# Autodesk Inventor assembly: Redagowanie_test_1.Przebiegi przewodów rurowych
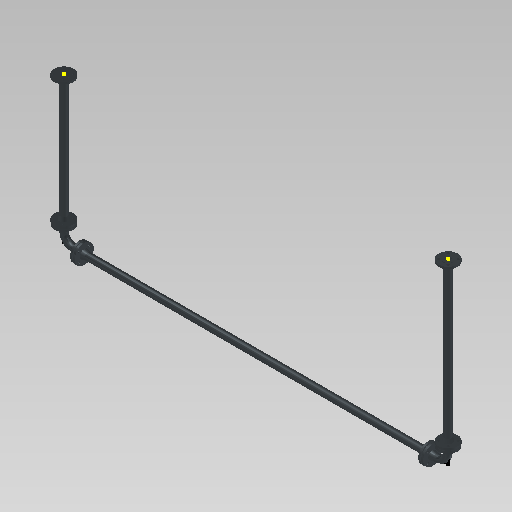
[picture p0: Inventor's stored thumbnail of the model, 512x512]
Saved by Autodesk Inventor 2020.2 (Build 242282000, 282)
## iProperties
ActiveState: False
Angle: UnInitValue
BendRadius: 12,700 mm
CouplingKey: UnInitValue
DefaultBendRadius: UnInitValue
Diameter: 1/2
DiameterType: Nominal
Elbow45Key: UnInitValue
Elbow90Key: UnInitValue
ElbowCustomKey: UnInitValue
EndFittingKey: v3#933069c9-73b6-4141-af99-628d4a97b2c2#1
Ending: UnInitValue
FittingMaterial: UnInitValue
FittingStandard: UnInitValue
FlangeKey: UnInitValue
Gap: UnInitValue
GasketKey: UnInitValue
ID: 1,27
IntermediateSegmentsInc: UnInitValue
IntermediateSegmentsMax: UnInitValue
IntermediateSegmentsMin: UnInitValue
IsButtWelded: UnInitValue
IsFlanged: UnInitValue
IsSelfDraining: UnInitValue
Material: UnInitValue
MixedUnits: UnInitValue
Name: Przewód hydrauliczny – złączki kołnierzowe SAE
OD: 2,2352
PipeKey: v3#d489867e-ac9b-47ea-b952-0a1b885f66be#4
PipeType: Flexible Hose
PipingComponentColor: As Material
RoundUpValue: 3,175 mm
RouteDirection45: UnInitValue
RouteDirection90: UnInitValue
Schedule: ID=0.5
ShowGap: UnInitValue
Standard: UnInitValue
StartFittingKey: v3#933069c9-73b6-4141-af99-628d4a97b2c2#1
SuppressEndFitting: False
SuppressStartFitting: False
TerminationSegmentsInc: UnInitValue
TerminationSegmentsMax: UnInitValue
TerminationSegmentsMin: UnInitValue
UseFlangsForCouplings: UnInitValue
UseSubASM: True
_ComponentInfo: <CS><C N="Pipe" R="1.117600" OR="1.117600" IR="0.635000" PL="PL" PartType="" SymKey="" PN="Parker Hydraulic Hose - No Skive 1/2"><CO N="1"><FE V="0"/><FD V="0"/
BendRadius: UnInitValue
CouplingKey: v3#52ad3977-2b89-4007-a6a6-7626bac0ae85#4
Elbow45Key: v3#5c2ab816-abcb-49a6-a106-4733af000f51#4
Elbow90Key: v3#160eac10-3e6f-4b5c-839c-61eee0d373dc#4
EndFittingKey: UnInitValue
ID: UnInitValue
IntermediateSegmentsInc: 2,540 mm
IntermediateSegmentsMax: 5080,000 mm
IntermediateSegmentsMin: 50,800 mm
IsButtWelded: False
IsFlanged: False
IsSelfDraining: False
MixedUnits: False
Name: ASME B36.10M-ASME B16.11 - Rury stalowe gwintowane
OD: UnInitValue
PipeKey: v3#4a736116-503a-44ad-a922-868ac6b46736#1
PipeType: Rigid Pipe
RoundUpValue: UnInitValue
RouteDirection45: True
RouteDirection90: True
Schedule: 30
StartFittingKey: UnInitValue
SuppressEndFitting: UnInitValue
SuppressStartFitting: UnInitValue
TerminationSegmentsInc: 2,540 mm
TerminationSegmentsMax: 5080,000 mm
TerminationSegmentsMin: 50,800 mm
UseSubASM: UnInitValue
_ComponentInfo: <CS><C N="Pipe" R="1.066800" IR="0.825500" PL="PL" PN="ASME B36.10M Pipe with Threaded Ends 1/2 - Schedule 30"><CO N="1"><FE V="0"/><FD V="1"/><ET V="Threaded"/
Name: Przewód hydrauliczny – bez złączek
SuppressEndFitting: True
SuppressStartFitting: True
Diameter: M40
Elbow45Key: v3#97879d80-057e-491b-840b-74a9b3a7cf63#17
Elbow90Key: v3#ace818b0-7b7c-4ad9-b19c-6da358a202c1#17
IntermediateSegmentsInc: 1,000 mm
IntermediateSegmentsMax: 5000,000 mm
IntermediateSegmentsMin: 60,000 mm
Name: DIN 2458/DIN 2605 - Rury stalowe spawane i łączniki
PipeKey: v3#dcef2839-8903-4c98-a96c-b861f5d9bb7f#98
Schedule: ID=30.7
TerminationSegmentsInc: 1,000 mm
TerminationSegmentsMax: 5000,000 mm
TerminationSegmentsMin: 60,000 mm
_ComponentInfo: <CS><C N="Pipe" R="2.415000" IR="1.535000" PL="PL" PN="DIN 2458 Pipe 48.3 x 8.8"><CO N="1"><FE V="2"/><FD V="0"/><ET V="Welded"/><NS V="M40"/><MA V="0.000000"/>
CouplingKey: v3#181262db-c004-4877-bc40-c64b931a44f6#3
Elbow45Key: v3#960407aa-00b9-4d72-aae7-d50595845cfd#3
Elbow90Key: v3#6c92b367-65e9-486b-b952-db434ae2548d#3
IntermediateSegmentsMin: 20,000 mm
Name: JIS G 3442/JIS B 2301 - Rury stalowe gwintowane ze stalowymi łącznikami
PipeKey: v3#9964fba4-9d5a-4d75-85a8-e38022ccdce1#2
Schedule: ID=16.1
TerminationSegmentsMin: 20,000 mm
_ComponentInfo: <CS><C N="Pipe" R="1.085000" IR="0.805000" PL="PL" PN="JIS G 3442 Pipe with Threaded Ends 21.7 x 2.8"><CO N="1"><FE V="0"/><FD V="1"/><ET V="Threaded"/><NS V="1
Angle: 92,00 deg
Diameter: 1
Elbow45Key: v3#bf26aa2a-f3dd-474c-8758-922a145c2b02#15
Elbow90Key: v3#3e93288f-9bb7-4e46-9d6b-544f8c20ca1c#3
ElbowCustomKey: v3#1f3bd44a-47ab-42f9-b3e0-74afa0c3f0ca#3
Gap: 2,388 mm
IntermediateSegmentsInc: 0.00001 in
IsButtWelded: True
IsSelfDraining: True
Name: ASME BPE - Rura stalowa kołnierzowa
PipeKey: v3#b10c956f-6fc6-429e-8056-0864a8581764#35
Schedule: ID=0.87
ShowGap: True
TerminationSegmentsInc: 0.00001 in
_ComponentInfo: <CS><C N="Pipe" R="1.270000" OR="1.270000" IR="1.104900" PL="PL" PartType="pipe" SymKey="" PN="ASTM A 269 Tube with Welded ends 1 x 0.87"><CO N="1"><FE V="2"/><
Diameter: 6
Elbow90Key: v3#97ecdcaf-8aa3-4fb0-8b6a-3da783de2ad5#108
Gap: 1,575 mm
IntermediateSegmentsMin: 76,200 mm
Name: ASTM A 53/A-ASME B16.9 - Rura stalowa ze szwem
PipeKey: v3#4ce5e9fa-6da0-4801-ac02-ee7a0fb518d6#77
RouteDirection45: False
Schedule: 40
TerminationSegmentsMin: 76,200 mm
_ComponentInfo: <CS><C N="Elbow90" ER="15.240000" S1="15.240000" S2="15.240000" D1="0.000000" D2="0.000000" PartType="fitting" SymKey="ELBW"><CO N="1"><FE V="2"/><FD V="0"/><ET
EndFittingKey: v3#c5e461f5-5e73-4f2e-8c1e-4358d4d6f46c#4
Name: Przewód hydrauliczny – gwint wewnętrzny - obrotowy
StartFittingKey: v3#c5e461f5-5e73-4f2e-8c1e-4358d4d6f46c#4
Manager: www.cadconsulting.pl
Company: Fabian Stasiak CAD Consulting
CouplingKey: v3#3edf83e2-464b-4b31-84c5-c329ffbf2a4f#5
Elbow45Key: v3#2f597a97-b15b-49d4-87cb-7bfe69eb62ee#5
Elbow90Key: v3#fbd68fd5-590c-4cb5-8c20-9e9bdd396a04#5
Name: DIN 8062/DIN 8063 - Rury i złączki PCV-U
PipeKey: v3#3d294dc7-89c3-4c37-a0ae-28c15a73bfd0#13
Schedule: 5
_ComponentInfo: <CS><C N="Pipe" R="2.000000" IR="1.700000" PL="PL" PN="DIN 8062 Pipe 40 x 3"><CO N="1"><FE V="0"/><FD V="0"/><ET V="Jointed"/><NS V="M40"/><MA V="8.000000"/><MI
EndFittingKey: v3#cc3bd835-95a2-497d-9893-176cd9c426f6#7
Name: Przewód hydrauliczny – gwint stożkowy wewnętrzny
StartFittingKey: v3#cc3bd835-95a2-497d-9893-176cd9c426f6#7
EndFittingKey: v3#b50cb43e-68c0-48ac-8e25-7ef224ce0e6c#3
Name: Przewód hydrauliczny – gwint zewnętrzny prosty
StartFittingKey: v3#b50cb43e-68c0-48ac-8e25-7ef224ce0e6c#3
CouplingKey: v3#eaa8de87-dc67-4eca-ba7e-4267a30f8f7f#2
Elbow45Key: v3#2769403e-a4fd-4a4c-8e4c-659ea845bd78#2
Elbow90Key: v3#c4513a61-3106-4a78-baf9-a1badd100245#2
IntermediateSegmentsMax: 2500,000 mm
Name: JIS K 6741/JIS K 6739 - Rury i złączki PCV-U
PipeKey: v3#45338dd0-af69-48c0-a2ed-8ade33a08701#5
Schedule: VP
TerminationSegmentsMax: 2500,000 mm
_ComponentInfo: <CS><C N="Pipe" R="2.400000" IR="2.040000" PL="PL" PN="JIS K 6741 Pipe VP 40"><CO N="1"><FE V="0"/><FD V="1"/><ET V="Jointed"/><NS V="M40"/><MA V="4.000000"/><M
CouplingKey: v3#7e56b2cb-a132-4546-b8a7-a14538454b94#3
Elbow45Key: v3#a96c5204-26e4-4bb2-b8f1-f0623fbc94bb#2
Elbow90Key: v3#b72bb08b-ad33-47cc-a03d-7f3d76c6616b#3
Name: ISO 7598/ISO 49 - Rury stalowe gwintowane ze stalowymi łącznikami
PipeKey: v3#1052637f-74b5-47f4-adeb-d4e8d3fa53b8#1
_ComponentInfo: <CS><C N="Pipe" R="1.065000" IR="0.805000" PL="PL" PN="ISO 7598 Tube with Threaded Ends DN15"><CO N="1"><FE V="0"/><FD V="1"/><ET V="Threaded"/><NS V="1/2"/><MA
EndFittingKey: v3#c8250148-a7b6-458b-b7bd-3b56763ca7cc#13
Name: Przewód hydrauliczny – gwint stożkowy zewnętrzny
StartFittingKey: v3#c8250148-a7b6-458b-b7bd-3b56763ca7cc#13
Elbow90Key: v3#6a678020-d9d9-4685-bba9-906b9a167083#10
FlangeKey: v3#24991861-26e3-4c21-a713-f46e314eddd5#10
GasketKey: v3#2a41914c-f5fb-4682-9c6a-1870d826d3d0#23
IsFlanged: True
Name: ASTM A 53/A 53M - Rura stalowa kołnierzowa/spawana doczołowo
UseFlangsForCouplings: False
_ComponentInfo: <CS><C N="Pipe" R="8.413750" OR="8.413750" IR="7.702550" PL="PL" PartType="pipe" SymKey="" PN="ASTM A 53/A 53M Pipe 6 - Schedule 40"><CO N="1"><FE V="2"/><FD V=
CouplingKey: v3#12b64993-10e6-4915-8315-0c0cce209ad0#8
Elbow45Key: v3#28e76e79-e22c-40ab-8be2-ff545b1407c5#8
Elbow90Key: v3#1f65ece3-c41a-48d4-8661-909ed34ade86#8
Name: JIS G 3458/JIS B 2316 - Rury stalowe spawane i łączniki
PipeKey: v3#da14b0ab-0b36-4851-8d66-8c9cd0bcbe86#23
Schedule: 80
_ComponentInfo: <CS><C N="Pipe" R="2.430000" IR="1.920000" PL="PL" PN="JIS G 3458 Pipe 40 A x Sch 80"><CO N="1"><FE V="0"/><FD V="1"/><ET V="Welded"/><NS V="M40"/><MA V="0.0000
CouplingKey: v3#ed415c76-4cec-44a3-ba67-72e47bf70384#4
Elbow45Key: v3#2e5fd082-3851-4eb0-bde1-6c7078a7d72b#4
Elbow90Key: v3#82a08401-12d7-413b-b7f9-9cf3b607be7b#4
IntermediateSegmentsMin: 25,400 mm
Name: ASTM A53/A53M-ASME B16.11 - Rury stalowe spawane
PipeKey: v3#4ce5e9fa-6da0-4801-ac02-ee7a0fb518d6#7
TerminationSegmentsMin: 25,400 mm
_ComponentInfo: <CS><C N="Pipe" R="1.066800" IR="0.789940" PL="PL" PN="ASTM A 53/A 53M Pipe 1/2 - Schedule 40"><CO N="1"><FE V="0"/><FD V="0"/><ET V="Welded"/><NS V="1/2"/><MA 
Created: 2014-08
Part Number: Redagowanie_test_1.Przebiegi przewodów rurowych
Document SubType Name: Tube & Pipe
Designer: F.Stasiak
Manufacturer: Standard
Standards Organization: Custom
Catalog Web Link: www.expertbooks.pl
USE_R9_BOM: False
FlangeKey: v3#c11442d2-c568-438f-a870-8ac9b5b636cb#10
Name: ASTM A 53/A-ASME B16.5 - Rura stalowa gwintowana kołnierzowa
PipeKey: v3#c5bd7d28-cdb3-4507-9f3d-c2787d93fe8a#40
_ComponentInfo: <CS><C N="Elbow90" ER="21.590000" S1="21.590000" S2="21.590000" D1="0.000000" D2="0.000000" PartType="fitting" SymKey="ELFL"><CO N="1"><FE V="2"/><FD V="1"/><ET
CouplingKey: v3#b06656e5-2b55-488c-bcf0-6a90c79c4683#2
Elbow45Key: v3#421a8b99-1721-409a-bc3b-c00889561754#1
Elbow90Key: v3#17490b17-1dd8-40fc-8de7-1a70c3bab2d7#1
IntermediateSegmentsMax: 2540,000 mm
Name: ISO 4065-ISO 3633 - Rury i złączki PCV
PipeKey: v3#4f84f716-5ba0-45ef-967a-c32c3d7345ce#70
Schedule: S40
TerminationSegmentsMax: 2540,000 mm
_ComponentInfo: <CS><C N="Pipe" R="2.000000" IR="1.950000" PL="PL" PN="ISO 4065 Pipe 40 x 0.5 S40"><CO N="1"><FE V="0"/><FD V="0"/><ET V="Jointed"/><NS V="M40"/><MA V="6.000000
CouplingKey: v3#771d4942-b9e7-43bc-9d41-ab12a9580492#3
Elbow45Key: v3#626cc28c-1a24-4045-be0d-40d896dc828d#3
Elbow90Key: v3#bc6b44ab-9235-4590-b699-74498030a1ff#3
Name: ANSI/ASME B36.19M-ASME B16.3 - Rury gwintowane ze stalowymi łącznikami
PipeKey: v3#323c0148-c750-449d-a0c6-11721f2a5046#1
Schedule: 40S
_ComponentInfo: <CS><C N="Pipe" R="1.066800" IR="0.789940" PL="PL" PN="ANSI/ASME B36.19M Pipe with Threaded Ends 1/2 - Schedule 40S"><CO N="1"><FE V="0"/><FD V="1"/><ET V="Thre
CouplingKey: v3#0dc1ae02-7bbf-4ccf-8498-581434b0a765#3
DefaultBendRadius: 50,800 mm
IntermediateSegmentsMin: 0,000 mm
Name: ASTM B 88-ASME B16.22 - Rury miedziane lutowane
PipeKey: v3#44b182c9-4bce-4825-bb4d-596143122252#7
PipeType: Tubing
Schedule: L
TerminationSegmentsMin: 0,000 mm
_ComponentInfo: <CS><C N="Pipe" R="0.793750" IR="0.692150" PL="PL" PN="ASTM B 88 Tube 1/2 - Type L"><CO N="1"><FE V="0"/><FD V="0"/><ET V="Soldered"/><NS V="1/2"/><MA V="2.5400
count: 53
Refkey_Axis1_Context: 2|0|0|0|1|0|0|0|
Refkey_Axis1: 6|0|0|0|44|0|0|0|78|0|65|0|77|0|69|0|83|0|10|0|67|0|111|0|108|0|111|0|114|0|115|0|10|0|49|0|58|0|10|0|10|0|69|0|78|0|68|0|10|0|0|0|
Refkey_Axis2_Context: 2|0|0|0|1|0|0|0|
Refkey_Axis2: 6|0|0|0|88|0|0|0|78|0|65|0|77|0|69|0|83|0|10|0|67|0|111|0|108|0|111|0|114|0|115|0|10|0|49|0|58|0|82|0|111|0|117|0|116|0|101|0|32|0|85|0|73|0|32|0|84|0|111|0|111
Refkey_Axis3_Context: 2|0|0|0|1|0|0|0|
Refkey_Axis3: 6|0|0|0|88|0|0|0|78|0|65|0|77|0|69|0|83|0|10|0|67|0|111|0|108|0|111|0|114|0|115|0|10|0|49|0|58|0|82|0|111|0|117|0|116|0|101|0|32|0|85|0|73|0|32|0|84|0|111|0|111
Refkey_Ext_Context: 2|0|0|0|1|0|0|0|
Refkey_Ext: 6|0|0|0|92|0|0|0|78|0|65|0|77|0|69|0|83|0|10|0|67|0|111|0|108|0|111|0|114|0|115|0|10|0|49|0|58|0|82|0|111|0|117|0|116|0|101|0|32|0|85|0|73|0|32|0|84|0|111|0|111
Refkey_Snap_Context: 2|0|0|0|1|0|0|0|
Refkey_Snap: 6|0|0|0|84|0|0|0|78|0|65|0|77|0|69|0|83|0|10|0|67|0|111|0|108|0|111|0|114|0|115|0|10|0|49|0|58|0|82|0|111|0|117|0|116|0|101|0|32|0|85|0|73|0|32|0|84|0|111|0|111
CouplingKey: v3#29993622-4c6a-437e-8b8c-43a0846f8735#1
Elbow45Key: v3#d7b5d569-4a12-4d65-ba55-12203d6ac7ed#1
Elbow90Key: v3#25d2a8db-6517-4627-a5a4-9d27e4d26b9b#1
Name: ASTM D 1785-ASTM D 2466 - Rury i złączki PCV
PipeKey: v3#4bf12049-4375-491b-8f13-d4ee0c517c57#1
_ComponentInfo: <CS><C N="Pipe" R="1.066800" IR="0.789940" PL="PL" PN="ASTM D 1785 Pipe 1/2 - Schedule 40"><CO N="1"><FE V="0"/><FD V="0"/><ET V="Jointed"/><NS V="1/2"/><MA V="
CouplingKey: v3#d2599e7a-1865-48da-a234-5418a1cd5dfe#3
Elbow45Key: v3#6ce5b1be-37aa-4928-b23a-0df64e6ddf38#2
Elbow90Key: v3#9fba244e-81ed-4fc6-a9ac-7eb372fa3ffe#3
Name: DIN 2458/DIN EN 10242 - Rury stalowe gwintowane i stalowe łączniki
PipeKey: v3#d689fd5f-ac5a-46d7-a883-3089b2f6e0a4#28
Schedule: ID=12.3
_ComponentInfo: <CS><C N="Pipe" R="1.065000" IR="0.615000" PL="PL" PN="DIN 2458 Pipe with Threaded Ends 21.3 x 4.5"><CO N="1"><FE V="0"/><FD V="1"/><ET V="Threaded"/><NS V="1/2
Author: F.Stasiak
Subject: Zbiór ćwiczeń. Autodesk Inventor 2020. Kurs Professional
ActiveState: True
Elbow45Key: v3#81684a3f-f2a4-4fe6-95b1-f067ddead22f#1
Elbow90Key: v3#451ae64e-c79d-4cba-b533-c09b8090ecb2#1
IntermediateSegmentsInc: 10,000 mm
IntermediateSegmentsMax: 9000,000 mm
IntermediateSegmentsMin: 1000,000 mm
Name: ISO 2531 - Rury żelazne kołnierzowe i łączniki
PipeKey: v3#f52fbdcb-ece8-4303-8b76-5dbe8c7f2f9c#16
Schedule: PN10
TerminationSegmentsInc: 10,000 mm
TerminationSegmentsMax: 9000,000 mm
TerminationSegmentsMin: 1000,000 mm
_ComponentInfo: <CS><C N="Pipe" R="2.700000" IR="2.000000" PL="PL" PN="ISO 2531 Pipe with Integrally Cast Flanges DN40 PN 10"><CO N="1"><FE V="0"/><FD V="0"/><ET V="Flanged"/><
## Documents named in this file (2)
- C:\2020_Kurs_Professional\R1 Rury\Redagowanie_test_1\AIP\Przewody rurowe\Redagowanie_test_1.Przebiegi przewodów rurowych.iam
- C:\2020_Kurs_Professional\R1 Rury\Redagowanie_test_1\AIP\Przewody rurowe\Przebieg01\Redagowanie_test_1.Przebieg01.iam
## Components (1 placed, 1 different names)
1. Przebieg01 [sub-assembly]
